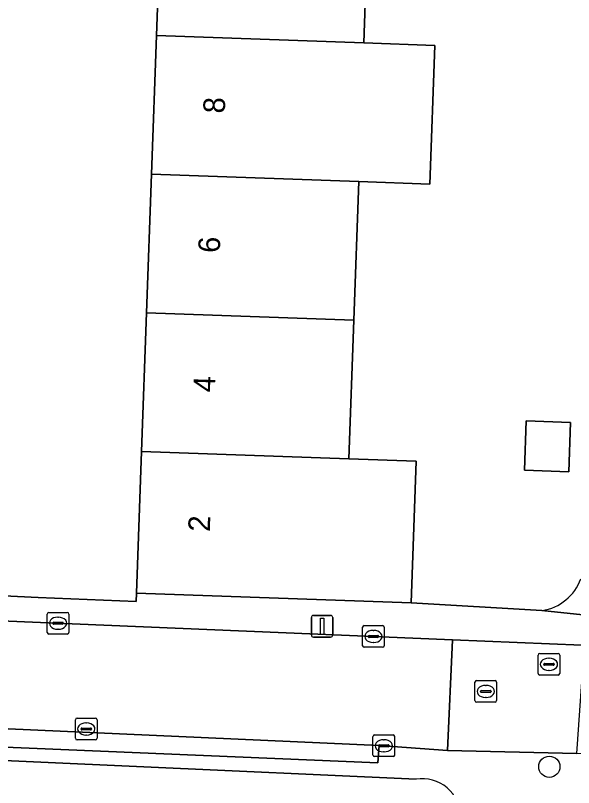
# Model space of a CAD drawing. Extents: x 160732 to 162107, y 387428 to 388479.
# Drawn here: x 161130.59 to 161156.38, y 387524.95 to 387560.59 of the extents above; entities that cross this region are included whole.
import ezdxf

# ---------------------------------------------------------------- set-up
doc = ezdxf.new("R2010")
doc.units = 0
for name, color, linetype in [('IMGEO_Boom', 7, 'Continuous'), ('IMGEO_Erf', 7, 'Continuous'), ('IMGEO_Kolk', 7, 'Continuous'), ('IMGEO_Lichtmast', 7, 'Continuous'), ('IMGEO_Pand', 7, 'Continuous'), ('IMGEO_Pand_nummerreeks', 7, 'Continuous'), ('IMGEO_Rijbaan_lokaal_open', 7, 'Continuous'), ('IMGEO_Rioolput', 7, 'Continuous'), ('IMGEO_Voetpad_open', 7, 'Continuous')]:
    doc.layers.add(name, color=color, linetype=linetype)

msp = doc.modelspace()

# ---------------------------------------------------------------- linework, layer by layer
at = {"layer": 'IMGEO_Boom'}
msp.add_circle((161155.258, 387525.908), 0.489, dxfattribs=at)
at = {"layer": 'IMGEO_Erf'}
for points in [[(161118.175, 387572.62), (161116.748, 387536.89), (161118.993, 387534.338), (161131.639, 387533.72), (161136.177, 387533.542), (161136.191, 387533.922), (161136.425, 387540.468), (161136.653, 387546.866), (161136.882, 387553.264), (161137.11, 387559.662), (161137.339, 387566.06)], [(161146.912, 387565.718), (161146.684, 387559.32), (161149.967, 387559.203), (161149.739, 387552.805), (161146.455, 387552.922), (161146.227, 387546.524), (161145.998, 387540.126), (161149.107, 387540.015), (161148.873, 387533.469), (161154.919, 387533.12)], [(161149.102, 387525.337), (161110.336, 387527.095), (161109.847, 387527.117), (161109.858, 387527.034)]]:
    msp.add_lwpolyline(points, dxfattribs=at)
msp.add_lwpolyline([(161154.112, 387539.602), (161154.193, 387541.87), (161156.234, 387541.797), (161156.153, 387539.529)], close=True, dxfattribs=at)
for centre, radius, start, end in [((161154.582, 387535.364), 2.27, 278.551, 340.0486), ((161149.391, 387523.617), 1.744, 358.8285, 99.5339)]:
    msp.add_arc(centre, radius, start, end, dxfattribs=at)
at = {"layer": 'IMGEO_Kolk'}
for p, q in [((161132.065, 387532.107), (161132.065, 387532.959)), ((161132.14, 387533.033), (161132.992, 387533.033)), ((161132.553, 387532.813), (161132.578, 387532.813)), ((161133.066, 387532.959), (161133.066, 387532.107)), ((161132.324, 387532.527), (161132.324, 387532.539)), ((161132.762, 387532.49), (161132.364, 387532.49)), ((161132.367, 387532.576), (161132.765, 387532.576)), ((161132.808, 387532.539), (161132.808, 387532.527)), ((161146.631, 387531.498), (161146.631, 387532.35)), ((161146.706, 387532.424), (161147.558, 387532.424)), ((161147.632, 387532.35), (161147.632, 387531.498)), ((161132.992, 387532.033), (161132.14, 387532.033)), ((161132.576, 387532.253), (161132.551, 387532.253)), ((161147.119, 387532.204), (161147.144, 387532.204)), ((161146.89, 387531.918), (161146.89, 387531.93)), ((161147.328, 387531.881), (161146.93, 387531.881)), ((161146.933, 387531.967), (161147.331, 387531.967)), ((161147.142, 387531.644), (161147.117, 387531.644)), ((161147.374, 387531.93), (161147.374, 387531.918)), ((161147.558, 387531.424), (161146.706, 387531.424)), ((161133.366, 387527.226), (161133.366, 387528.078)), ((161133.441, 387528.152), (161134.293, 387528.152)), ((161134.367, 387528.078), (161134.367, 387527.226)), ((161133.854, 387527.932), (161133.879, 387527.932)), ((161133.625, 387527.646), (161133.625, 387527.658)), ((161134.063, 387527.609), (161133.665, 387527.609)), ((161133.668, 387527.695), (161134.066, 387527.695)), ((161133.877, 387527.372), (161133.852, 387527.372)), ((161134.109, 387527.658), (161134.109, 387527.646)), ((161147.187, 387527.377), (161148.039, 387527.377)), ((161134.293, 387527.152), (161133.441, 387527.152)), ((161147.112, 387526.451), (161147.112, 387527.303)), ((161147.6, 387527.157), (161147.625, 387527.157)), ((161148.113, 387527.303), (161148.113, 387526.451)), ((161147.371, 387526.871), (161147.371, 387526.883)), ((161147.809, 387526.834), (161147.411, 387526.834)), ((161147.414, 387526.92), (161147.812, 387526.92)), ((161147.855, 387526.883), (161147.855, 387526.871)), ((161148.039, 387526.377), (161147.187, 387526.377)), ((161147.623, 387526.597), (161147.598, 387526.597))]:
    msp.add_line(p, q, dxfattribs=at)
for points in [[(161132.065, 387532.107), (161132.065, 387532.959)], [(161132.14, 387533.033), (161132.992, 387533.033)], [(161133.066, 387532.959), (161133.066, 387532.107)], [(161146.631, 387531.498), (161146.631, 387532.35)], [(161146.706, 387532.424), (161147.558, 387532.424)], [(161147.632, 387532.35), (161147.632, 387531.498)], [(161132.992, 387532.033), (161132.14, 387532.033)], [(161147.558, 387531.424), (161146.706, 387531.424)], [(161133.366, 387527.226), (161133.366, 387528.078)], [(161133.441, 387528.152), (161134.293, 387528.152)], [(161134.367, 387528.078), (161134.367, 387527.226)], [(161147.187, 387527.377), (161148.039, 387527.377)], [(161134.293, 387527.152), (161133.441, 387527.152)], [(161147.112, 387526.451), (161147.112, 387527.303)], [(161148.113, 387527.303), (161148.113, 387526.451)], [(161148.039, 387526.377), (161147.187, 387526.377)]]:
    msp.add_lwpolyline(points, dxfattribs=at)
for centre, radius, start, end in [((161132.142, 387532.957), 0.0765, 91.552, 178.448), ((161132.142, 387532.957), 0.0765, 91.552, 178.448), ((161132.99, 387532.957), 0.0765, 1.552, 88.448), ((161132.99, 387532.957), 0.0765, 1.552, 88.448), ((161132.364, 387532.536), 0.0403, 85.8775, 175.7526), ((161132.361, 387532.526), 0.0366, 178.938, 274.7102), ((161132.765, 387532.533), 0.043, 264.8664, 352.4533), ((161132.769, 387532.538), 0.0386, 1.7309, 96.639), ((161146.708, 387532.348), 0.0765, 91.552, 178.448), ((161146.708, 387532.348), 0.0765, 91.552, 178.448), ((161147.556, 387532.348), 0.0765, 1.552, 88.448), ((161147.556, 387532.348), 0.0765, 1.552, 88.448), ((161132.142, 387532.109), 0.0765, 181.552, 268.448), ((161132.142, 387532.109), 0.0765, 181.552, 268.448), ((161132.99, 387532.109), 0.0765, 271.552, 358.448), ((161132.99, 387532.109), 0.0765, 271.552, 358.448), ((161146.93, 387531.927), 0.0403, 85.8775, 175.7526), ((161146.927, 387531.917), 0.0366, 178.938, 274.7102), ((161147.331, 387531.924), 0.043, 264.8664, 352.4533), ((161147.335, 387531.929), 0.0386, 1.7309, 96.639), ((161146.708, 387531.5), 0.0765, 181.552, 268.448), ((161146.708, 387531.5), 0.0765, 181.552, 268.448), ((161147.556, 387531.5), 0.0765, 271.552, 358.448), ((161147.556, 387531.5), 0.0765, 271.552, 358.448), ((161133.443, 387528.076), 0.0765, 91.552, 178.448), ((161133.443, 387528.076), 0.0765, 91.552, 178.448), ((161134.291, 387528.076), 0.0765, 1.552, 88.448), ((161134.291, 387528.076), 0.0765, 1.552, 88.448), ((161133.665, 387527.655), 0.0403, 85.8775, 175.7526), ((161133.662, 387527.645), 0.0366, 178.938, 274.7102), ((161134.066, 387527.652), 0.043, 264.8664, 352.4533), ((161134.07, 387527.657), 0.0386, 1.7309, 96.639), ((161147.189, 387527.301), 0.0765, 91.552, 178.448), ((161147.189, 387527.301), 0.0765, 91.552, 178.448), ((161148.037, 387527.301), 0.0765, 1.552, 88.448), ((161148.037, 387527.301), 0.0765, 1.552, 88.448), ((161133.443, 387527.228), 0.0765, 181.552, 268.448), ((161133.443, 387527.228), 0.0765, 181.552, 268.448), ((161134.291, 387527.228), 0.0765, 271.552, 358.448), ((161134.291, 387527.228), 0.0765, 271.552, 358.448), ((161147.411, 387526.88), 0.0403, 85.8775, 175.7526), ((161147.408, 387526.87), 0.0366, 178.938, 274.7102), ((161147.812, 387526.877), 0.043, 264.8664, 352.4533), ((161147.816, 387526.882), 0.0386, 1.7309, 96.639), ((161147.189, 387526.453), 0.0765, 181.552, 268.448), ((161147.189, 387526.453), 0.0765, 181.552, 268.448), ((161148.037, 387526.453), 0.0765, 271.552, 358.448), ((161148.037, 387526.453), 0.0765, 271.552, 358.448)]:
    msp.add_arc(centre, radius, start, end, dxfattribs=at)
for centre, major_axis, ratio, start_param, end_param in [((161132.552, 387532.533), (-0.387, 0.002), 0.722429, 4.712389, 7.853982), ((161132.577, 387532.533), (-0.39, 0.002), 0.717154, 1.570796, 4.712389), ((161147.118, 387531.924), (-0.387, 0.002), 0.722429, 4.712389, 7.853982), ((161147.143, 387531.924), (-0.39, 0.002), 0.717154, 1.570796, 4.712389), ((161133.853, 387527.652), (-0.387, 0.002), 0.722429, 4.712389, 7.853982), ((161133.878, 387527.652), (-0.39, 0.002), 0.717154, 1.570796, 4.712389), ((161147.599, 387526.877), (-0.387, 0.002), 0.722429, 4.712389, 7.853982), ((161147.624, 387526.877), (-0.39, 0.002), 0.717154, 1.570796, 4.712389)]:
    msp.add_ellipse(centre, major_axis=major_axis, ratio=ratio, start_param=start_param, end_param=end_param, dxfattribs=at)
at = {"layer": 'IMGEO_Lichtmast'}
for p, q in [((161144.264, 387531.995), (161144.264, 387532.795)), ((161144.264, 387532.795), (161144.264, 387531.995)), ((161144.364, 387532.895), (161145.154, 387532.895)), ((161145.154, 387532.895), (161144.364, 387532.895)), ((161145.254, 387532.795), (161145.254, 387531.995)), ((161145.254, 387531.995), (161145.254, 387532.795)), ((161145.154, 387531.895), (161144.364, 387531.895)), ((161144.364, 387531.895), (161145.154, 387531.895))]:
    msp.add_line(p, q, dxfattribs=at)
msp.add_lwpolyline([(161144.684, 387532.77), (161144.834, 387532.77), (161144.834, 387532.02), (161144.684, 387532.02), (161144.684, 387532.77)], dxfattribs=at)
for centre, start, end in [((161144.364, 387532.795), 90, 180), ((161144.364, 387532.795), 90, 180), ((161145.154, 387532.795), 0, 90), ((161145.154, 387532.795), 360, 90), ((161144.364, 387531.995), 180, 270), ((161144.364, 387531.995), 180, 270), ((161145.154, 387531.995), 270, 0), ((161145.154, 387531.995), 270, 0)]:
    msp.add_arc(centre, 0.1, start, end, dxfattribs=at)
at = {"layer": 'IMGEO_Pand'}
for points in [[(161137.339, 387566.06), (161137.11, 387559.662), (161146.684, 387559.32), (161146.912, 387565.718)], [(161146.455, 387552.922), (161149.739, 387552.805), (161149.967, 387559.203), (161146.684, 387559.32), (161137.11, 387559.662), (161136.882, 387553.264)], [(161146.227, 387546.524), (161146.455, 387552.922), (161136.882, 387553.264), (161136.653, 387546.866)], [(161136.653, 387546.866), (161136.425, 387540.468), (161145.998, 387540.126), (161146.227, 387546.524)], [(161154.112, 387539.602), (161156.153, 387539.529), (161156.234, 387541.797), (161154.193, 387541.87)], [(161148.873, 387533.469), (161149.107, 387540.015), (161145.998, 387540.126), (161136.425, 387540.468), (161136.191, 387533.922)]]:
    msp.add_lwpolyline(points, close=True, dxfattribs=at)
at = {"layer": 'IMGEO_Rijbaan_lokaal_open'}
msp.add_lwpolyline([(161110.371, 387528.545), (161147.402, 387526.893), (161150.551, 387526.662), (161150.782, 387531.772), (161118.93, 387533.102)], dxfattribs=at)
msp.add_lwpolyline([(161150.551, 387526.662), (161156.521, 387526.524), (161156.756, 387529.831), (161156.757, 387531.52), (161150.782, 387531.772)], close=True, dxfattribs=at)
at = {"layer": 'IMGEO_Rioolput'}
for p, q in [((161154.74, 387530.212), (161154.74, 387531.064)), ((161154.815, 387531.138), (161155.667, 387531.138)), ((161155.741, 387531.064), (161155.741, 387530.212)), ((161154.999, 387530.632), (161154.999, 387530.644)), ((161155.437, 387530.595), (161155.039, 387530.595)), ((161155.042, 387530.681), (161155.44, 387530.681)), ((161155.228, 387530.918), (161155.253, 387530.918)), ((161155.483, 387530.644), (161155.483, 387530.632)), ((161155.251, 387530.358), (161155.226, 387530.358)), ((161151.897, 387529.886), (161152.749, 387529.886)), ((161155.667, 387530.138), (161154.815, 387530.138)), ((161151.822, 387528.96), (161151.822, 387529.812)), ((161152.31, 387529.666), (161152.335, 387529.666)), ((161152.823, 387529.812), (161152.823, 387528.96)), ((161152.081, 387529.38), (161152.081, 387529.392)), ((161152.519, 387529.343), (161152.121, 387529.343)), ((161152.124, 387529.429), (161152.522, 387529.429)), ((161152.565, 387529.392), (161152.565, 387529.38)), ((161152.749, 387528.886), (161151.897, 387528.886)), ((161152.333, 387529.106), (161152.308, 387529.106))]:
    msp.add_line(p, q, dxfattribs=at)
for points in [[(161154.74, 387530.212), (161154.74, 387531.064)], [(161154.815, 387531.138), (161155.667, 387531.138)], [(161155.741, 387531.064), (161155.741, 387530.212)], [(161151.897, 387529.886), (161152.749, 387529.886)], [(161155.667, 387530.138), (161154.815, 387530.138)], [(161151.822, 387528.96), (161151.822, 387529.812)], [(161152.823, 387529.812), (161152.823, 387528.96)], [(161152.749, 387528.886), (161151.897, 387528.886)]]:
    msp.add_lwpolyline(points, dxfattribs=at)
for centre, radius, start, end in [((161154.817, 387531.062), 0.0765, 91.552, 178.448), ((161154.817, 387531.062), 0.0765, 91.552, 178.448), ((161155.665, 387531.062), 0.0765, 1.552, 88.448), ((161155.665, 387531.062), 0.0765, 1.552, 88.448), ((161155.039, 387530.641), 0.0403, 85.8775, 175.7526), ((161155.036, 387530.631), 0.0366, 178.938, 274.7102), ((161155.44, 387530.638), 0.043, 264.8664, 352.4533), ((161155.444, 387530.643), 0.0386, 1.7309, 96.639), ((161154.817, 387530.214), 0.0765, 181.552, 268.448), ((161154.817, 387530.214), 0.0765, 181.552, 268.448), ((161155.665, 387530.214), 0.0765, 271.552, 358.448), ((161155.665, 387530.214), 0.0765, 271.552, 358.448), ((161151.899, 387529.81), 0.0765, 91.552, 178.448), ((161151.899, 387529.81), 0.0765, 91.552, 178.448), ((161152.747, 387529.81), 0.0765, 1.552, 88.448), ((161152.747, 387529.81), 0.0765, 1.552, 88.448), ((161152.121, 387529.389), 0.0403, 85.8775, 175.7526), ((161152.118, 387529.379), 0.0366, 178.938, 274.7102), ((161152.522, 387529.386), 0.043, 264.8664, 352.4533), ((161152.526, 387529.391), 0.0386, 1.7309, 96.639), ((161151.899, 387528.962), 0.0765, 181.552, 268.448), ((161151.899, 387528.962), 0.0765, 181.552, 268.448), ((161152.747, 387528.962), 0.0765, 271.552, 358.448), ((161152.747, 387528.962), 0.0765, 271.552, 358.448)]:
    msp.add_arc(centre, radius, start, end, dxfattribs=at)
for centre, major_axis, ratio, start_param, end_param in [((161155.227, 387530.638), (-0.387, 0.002), 0.722429, 4.712389, 7.853982), ((161155.252, 387530.638), (-0.39, 0.002), 0.717154, 1.570796, 4.712389), ((161152.309, 387529.386), (-0.387, 0.002), 0.722429, 4.712389, 7.853982), ((161152.334, 387529.386), (-0.39, 0.002), 0.717154, 1.570796, 4.712389)]:
    msp.add_ellipse(centre, major_axis=major_axis, ratio=ratio, start_param=start_param, end_param=end_param, dxfattribs=at)
at = {"layer": 'IMGEO_Voetpad_open'}
for points in [[(161160.169, 387532.563), (161154.919, 387533.12), (161148.873, 387533.469), (161136.191, 387533.922), (161136.177, 387533.542), (161131.639, 387533.72), (161118.993, 387534.338), (161116.748, 387536.89), (161118.175, 387572.62), (161118.779, 387585.972)], [(161118.93, 387533.102), (161150.782, 387531.772), (161156.757, 387531.52), (161185.233, 387530.24)], [(161154.919, 387533.12), (161160.169, 387532.563)], [(161110.347, 387527.357), (161110.352, 387527.649), (161147.335, 387526.094), (161147.402, 387526.893), (161110.371, 387528.545)], [(161157.05, 387526.491), (161156.521, 387526.524), (161150.551, 387526.662), (161147.402, 387526.893), (161147.335, 387526.094), (161110.352, 387527.649), (161110.347, 387527.357), (161110.336, 387527.095), (161149.102, 387525.337)]]:
    msp.add_lwpolyline(points, dxfattribs=at)
for centre, radius, start, end in [((161154.582, 387535.364), 2.27, 278.551, 340.0486), ((161149.391, 387523.617), 1.744, 358.8285, 99.5339)]:
    msp.add_arc(centre, radius, start, end, dxfattribs=at)

# ---------------------------------------------------------------- texts
at = {"layer": 'IMGEO_Pand_nummerreeks'}
for s, p in [('8', (161140.264, 387556.056)), ('6', (161140.034, 387549.617)), ('4', (161139.804, 387543.182)), ('2', (161139.573, 387536.745))]:
    msp.add_text(s, height=1, rotation=87.9542, dxfattribs=at).set_placement(p)

doc.saveas('drawing.dxf')
